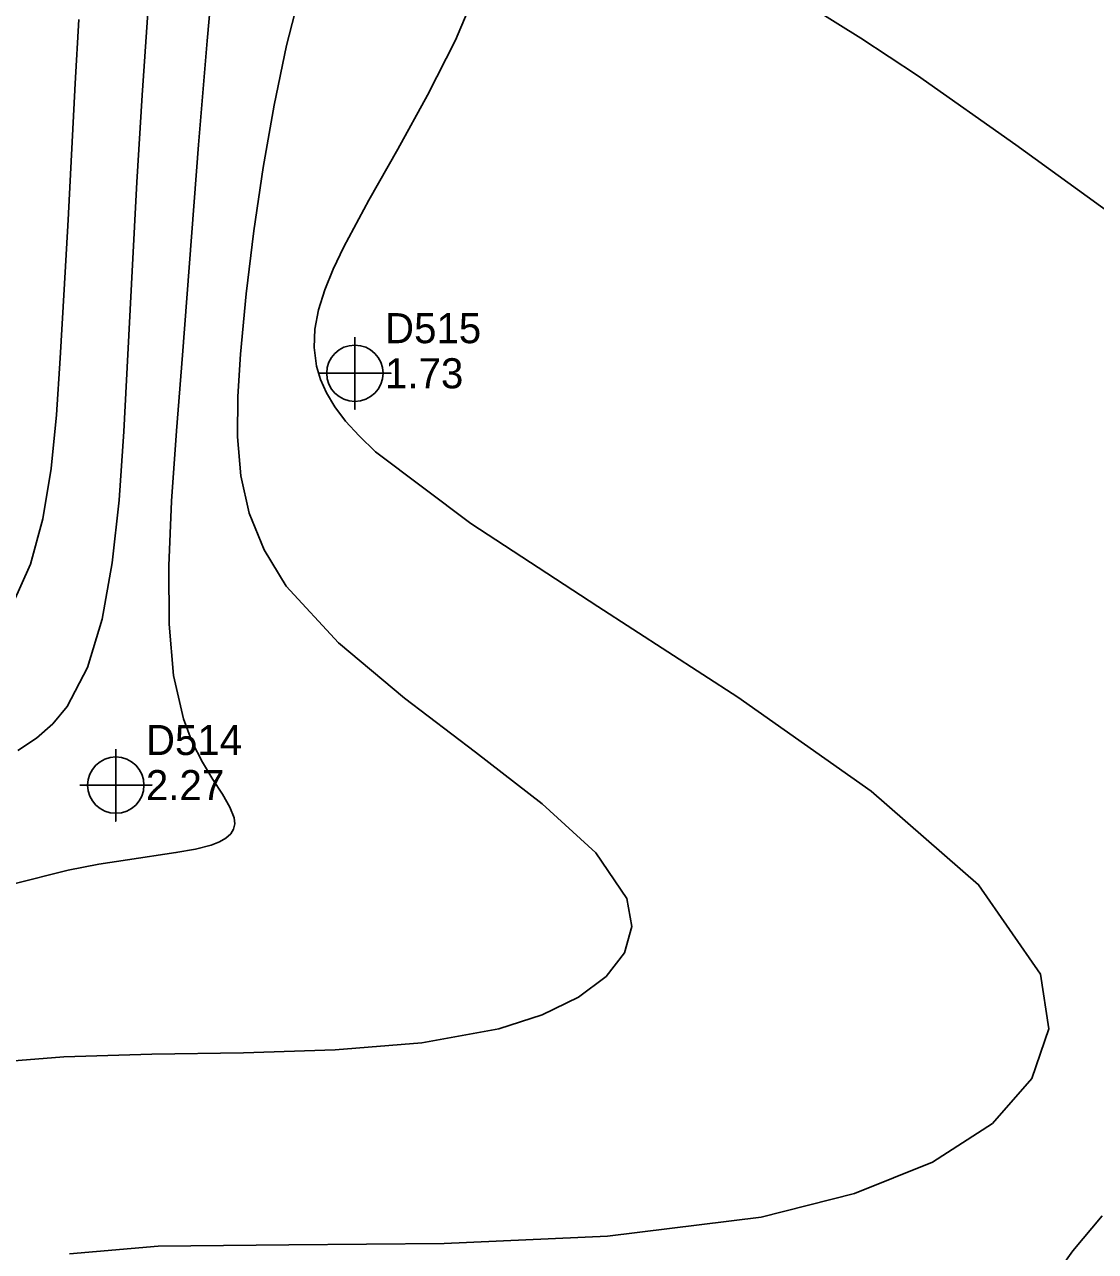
# Model space of a CAD drawing. Extents: x 2356077 to 2359823, y 225951 to 227822.
# Drawn here: x 2357094.1 to 2357183, y 226739.1 to 226841 of the extents above; entities that cross this region are included whole.
import ezdxf

# ---------------------------------------------------------------- set-up
doc = ezdxf.new("R2010")
doc.units = 0
for name, color, linetype in [('DTM Contours Major', 7, 'Continuous'), ('DTM Contours Minor', 7, 'Continuous'), ('Exist DTM Regular Point CELL', 7, 'Continuous'), ('Exist DTM Regular Point Cogo Elevation', 7, 'Continuous'), ('Exist DTM Regular Point Cogo Number', 7, 'Continuous')]:
    doc.layers.add(name, color=color, linetype=linetype)

msp = doc.modelspace()

# ---------------------------------------------------------------- linework, layer by layer
at = {"layer": 'DTM Contours Major'}
msp.add_lwpolyline([(2357117.01, 226843.81), (2357115.85, 226839.25), (2357114.82, 226834.31), (2357113.91, 226829.13), (2357113.13, 226823.86), (2357112.5, 226818.63), (2357112.03, 226813.6), (2357111.81, 226810.09), (2357111.78, 226806.74), (2357112.06, 226803.51), (2357112.75, 226800.39), (2357113.98, 226797.34), (2357115.83, 226794.34), (2357120.18, 226789.63), (2357125.66, 226785.02), (2357131.55, 226780.55), (2357137.09, 226776.25), (2357141.53, 226772.18), (2357144.13, 226768.37), (2357144.52, 226766.04), (2357143.92, 226763.87), (2357142.41, 226761.91), (2357140.1, 226760.17), (2357137.09, 226758.71), (2357133.48, 226757.54), (2357127.08, 226756.39), (2357119.89, 226755.8), (2357112.29, 226755.55), (2357104.66, 226755.44), (2357097.35, 226755.22), (2357090.76, 226754.7)], dxfattribs=at)
at = {"layer": 'DTM Contours Minor'}
for points in [[(2357109.98, 226847.72), (2357109.25, 226839.65), (2357108.55, 226830.99), (2357107.2, 226813.52), (2357106.7, 226807.25), (2357106.3, 226801.39), (2357106.07, 226796.01), (2357106.1, 226791.17), (2357106.47, 226786.91), (2357107.28, 226783.3), (2357108.02, 226781.38), (2357108.87, 226779.71), (2357109.74, 226778.27), (2357110.53, 226777.04), (2357111.15, 226775.98), (2357111.51, 226775.09), (2357111.56, 226774.59), (2357111.46, 226774.14), (2357111.22, 226773.74), (2357110.82, 226773.39), (2357110.28, 226773.08), (2357109.6, 226772.81), (2357108.29, 226772.48), (2357106.67, 226772.19), (2357102.64, 226771.6), (2357100.27, 226771.22), (2357097.7, 226770.72), (2357093.09, 226769.57)], [(2357131.83, 226844.32), (2357129.89, 226839.71), (2357127.56, 226835.12), (2357125.09, 226830.65), (2357122.69, 226826.41), (2357120.61, 226822.53), (2357119.73, 226820.68), (2357119.02, 226818.94), (2357118.5, 226817.28), (2357118.21, 226815.69), (2357118.15, 226814.15), (2357118.35, 226812.62), (2357118.68, 226811.51), (2357119.18, 226810.39), (2357119.87, 226809.23), (2357120.76, 226808.05), (2357121.89, 226806.81), (2357123.25, 226805.5), (2357131.15, 226799.53), (2357141.71, 226792.63), (2357153.33, 226785.11), (2357164.41, 226777.3), (2357173.33, 226769.52), (2357178.49, 226762.08), (2357179.17, 226757.56), (2357177.77, 226753.41), (2357174.48, 226749.69), (2357169.5, 226746.48), (2357163.03, 226743.87), (2357155.27, 226741.91), (2357142.51, 226740.31), (2357128.95, 226739.72), (2357116.04, 226739.61), (2357105.19, 226739.49), (2357097.83, 226738.86)], [(2357155.26, 226845.07), (2357163.55, 226839.86), (2357168.27, 226836.76), (2357176.42, 226831), (2357185.07, 226824.75)], [(2357098.59, 226841.42), (2357098.29, 226836.11), (2357097.7, 226824.76), (2357097.39, 226818.98), (2357097.06, 226813.28), (2357096.74, 226808.57), (2357096.3, 226804.1), (2357095.61, 226799.93), (2357094.58, 226796.15), (2357093.1, 226792.82)], [(2357104.33, 226841.97), (2357103.87, 226835.13), (2357103.43, 226827.89), (2357103.02, 226820.5), (2357102.33, 226807.18), (2357101.94, 226801.49), (2357101.38, 226796.26), (2357100.55, 226791.58), (2357099.33, 226787.57), (2357097.62, 226784.33), (2357096.43, 226782.9), (2357095.07, 226781.7), (2357093.53, 226780.67)], [(2357183.6, 226742.01), (2357181.16, 226739.1), (2357179.11, 226736.22)]]:
    msp.add_lwpolyline(points, dxfattribs=at)
at = {"layer": 'Exist DTM Regular Point CELL'}
for points in [[(2357121.53, 226815.02), (2357121.53, 226809.02), (2357121.53, 226812.02), (2357124.53, 226812.02), (2357118.53, 226812.02)], [(2357101.67, 226780.8), (2357101.67, 226774.8), (2357101.67, 226777.8), (2357104.67, 226777.8), (2357098.67, 226777.8)]]:
    msp.add_lwpolyline(points, dxfattribs=at)
for centre in [(2357121.53, 226812.02), (2357101.67, 226777.8)]:
    msp.add_circle(centre, 2.34, dxfattribs=at)

# ---------------------------------------------------------------- texts
at = {"layer": 'Exist DTM Regular Point Cogo Elevation'}
for s, p in [('1.73', (2357124.03, 226810.77)), ('2.27', (2357104.17, 226776.55))]:
    msp.add_text(s, height=2.5, dxfattribs=at).set_placement(p)
at = {"layer": 'Exist DTM Regular Point Cogo Number'}
for s, p in [('D515', (2357124.03, 226814.52)), ('D514', (2357104.17, 226780.3))]:
    msp.add_text(s, height=2.5, dxfattribs=at).set_placement(p)

doc.saveas('drawing.dxf')
